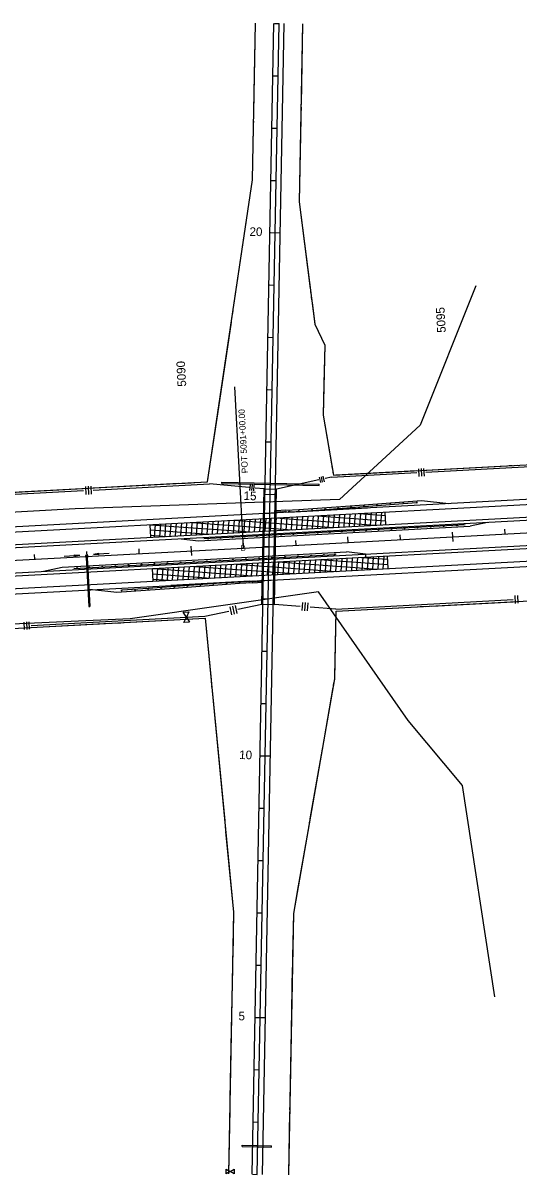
# Model space of a CAD drawing. Extents: x 192699 to 285914, y 194342 to 233219.
# Drawn here: x 253319 to 254267, y 223744 to 225946 of the extents above; entities that cross this region are included whole.
import ezdxf

# ---------------------------------------------------------------- set-up
doc = ezdxf.new("R2010")
doc.units = 0
for name, color, linetype in [('CENT LINE', 7, 'Continuous'), ('CURVE DATA', 7, 'Continuous'), ('DRAINAGE', 7, 'Continuous'), ('DRAINAGE ARROWS', 7, 'Continuous'), ('Flood Plain', 7, 'Continuous'), ('GUARDRAIL', 7, 'Continuous'), ('PAVEMENT TRANSITION', 7, 'Continuous'), ('R-W - CofA', 7, 'Continuous'), ('R_Proposed Guardrail', 7, 'Continuous'), ('R_Water Annot', 7, 'Continuous'), ('ROAD', 7, 'Continuous'), ('SHOULDER', 7, 'Continuous'), ('STATIONING1', 7, 'Continuous'), ('STATIONING2', 7, 'Continuous'), ('TEXT', 7, 'Continuous')]:
    doc.layers.add(name, color=color, linetype=linetype)

msp = doc.modelspace()

# ---------------------------------------------------------------- linework, layer by layer
at = {"layer": 'CENT LINE'}
for p, q in [((253766.8, 223745.2), (253808.4, 225944.8)), ((253740.3, 224942.3), (269263.7, 225774)), ((250998.2, 224795.4), (253740.3, 224942.3))]:
    msp.add_line(p, q, dxfattribs=at)
at = {"layer": 'DRAINAGE'}
for p, q in [((253698.8, 225067.9), (253884.8, 225064.4)), ((253698.8, 225065.4), (253884.7, 225061.9)), ((253439.8, 224924.2), (253444.8, 224830.4)), ((253441.8, 224924.3), (253446.8, 224830.5)), ((253737.8, 223798.5), (253793.8, 223797.4)), ((253737.9, 223801), (253793.9, 223799.9))]:
    msp.add_line(p, q, dxfattribs=at)
for points in [[(253698.8, 225065.4), (253698.8, 225067.9)], [(253884.7, 225061.9), (253884.8, 225064.4)], [(253444.8, 224830.4), (253446.8, 224830.5)], [(253737.8, 223798.5), (253737.9, 223801)], [(253793.8, 223797.4), (253793.9, 223799.9)]]:
    msp.add_lwpolyline(points, dxfattribs=at)
msp.add_lwpolyline([(253438.8, 224924.2), (253442.8, 224924.4), (253442.6, 224928.4), (253438.6, 224928.2)], close=True, dxfattribs=at)
at = {"layer": 'DRAINAGE ARROWS'}
for p, q in [((253417.4, 224929.5), (253427.5, 224928.5)), ((253417.5, 224926.5), (253417.4, 224929.5)), ((253417.4, 224929.3), (253425.8, 224928.5)), ((253417.4, 224929), (253424.1, 224928.4)), ((253417.4, 224928.8), (253422.4, 224928.3)), ((253417.4, 224928.5), (253420.7, 224928.2)), ((253417.5, 224926.5), (253427.5, 224928.5)), ((253417.5, 224926.8), (253425.8, 224928.5)), ((253417.5, 224927), (253424.1, 224928.4)), ((253417.5, 224927.3), (253422.4, 224928.3)), ((253417.5, 224928.3), (253419, 224928.1)), ((253417.5, 224927.5), (253420.7, 224928.2)), ((253417.5, 224927.8), (253419, 224928.1)), ((253463.6, 224932), (253453.7, 224930)), ((253463.8, 224929), (253453.7, 224930)), ((253463.7, 224931.8), (253455.4, 224930.1)), ((253463.8, 224929.3), (253455.4, 224930.1)), ((253463.7, 224931.5), (253457.1, 224930.1)), ((253463.8, 224929.5), (253457.1, 224930.1)), ((253463.7, 224931.3), (253458.8, 224930.2)), ((253463.8, 224929.8), (253458.8, 224930.2)), ((253463.7, 224931), (253460.5, 224930.3)), ((253463.7, 224930), (253460.5, 224930.3)), ((253463.7, 224930.8), (253462.1, 224930.4)), ((253463.7, 224930.3), (253462.1, 224930.4)), ((253463.8, 224929), (253463.6, 224932))]:
    msp.add_line(p, q, dxfattribs=at)
at = {"layer": 'Flood Plain'}
for points in [[(254184.2, 225443.4), (254077.7, 225177), (253923.8, 225034.9), (253418.6, 225017.1), (252417.7, 224961.1), (251507.7, 224918.6), (250580.7, 224854.4), (250428.4, 224837.7), (250447.9, 224645.3)], [(254220.9, 224084.6), (254158.8, 224488.6), (254055.2, 224612.9), (253883.9, 224858.7), (253524.1, 224806.8), (252494.8, 224760.4), (251539.4, 224719), (250710.5, 224664.9), (250448.5, 224645.5)]]:
    msp.add_lwpolyline(points, dxfattribs=at)
at = {"layer": 'GUARDRAIL'}
for p, q in [((253778.7, 225008.5), (253802.7, 225009.8)), ((253826.5, 225011), (253977.4, 225019.1)), ((253752.5, 224878.9), (253601.5, 224870.8)), ((253776.3, 224880.2), (253800.3, 224881.4))]:
    msp.add_line(p, q, dxfattribs=at)
at = {"layer": 'PAVEMENT TRANSITION'}
for p, q in [((253862.1, 224978.9), (253863.9, 225003)), ((253872.2, 224979.4), (253873.9, 225003.6)), ((253881.4, 225004), (254012.2, 224994.5)), ((253882.3, 224980), (253884, 225004.1)), ((253892.3, 224980.5), (253894.1, 225004.6)), ((253902.4, 224981), (253904.1, 225005.2)), ((253912.5, 224981.6), (253914.2, 225005.7)), ((253922.5, 224982.1), (253924.3, 225006.3)), ((253932.6, 224982.7), (253934.3, 225006.8)), ((253942.7, 224983.2), (253944.4, 225007.3)), ((253952.7, 224983.7), (253954.5, 225007.9)), ((253961.2, 225008.2), (254011.6, 225004.6)), ((253962.8, 224984.3), (253964.5, 225008.4)), ((253972.9, 224984.8), (253974.6, 225009)), ((253982.9, 224985.4), (253984.7, 225009.5)), ((253993, 224985.9), (253994.7, 225010)), ((254003, 224986.4), (254004.8, 225010.6)), ((254012.6, 224987), (254011.3, 225010.9)), ((253563.2, 224962.9), (253561.9, 224986.8)), ((253561.9, 224986.8), (253561.9, 224986.8)), ((253561.9, 224986.8), (253561.9, 224986.8)), ((253561.9, 224986.8), (253753.4, 224973.1)), ((253570.3, 224963.3), (253572, 224987.4)), ((253580.3, 224963.8), (253582.1, 224987.9)), ((253590.4, 224964.3), (253592.1, 224988.5)), ((253600.5, 224964.9), (253602.2, 224989)), ((253610.5, 224965.4), (253612.3, 224989.5)), ((253620.6, 224966), (253622.3, 224990.1)), ((253630.7, 224966.5), (253632.4, 224990.6)), ((253640.7, 224967), (253642.5, 224991.2)), ((253641.8, 224991.1), (253833.2, 224977.3)), ((253650.8, 224967.6), (253652.5, 224991.7)), ((253660.8, 224968.1), (253662.6, 224992.2)), ((253670.9, 224968.6), (253672.7, 224992.8)), ((253681, 224969.2), (253682.7, 224993.3)), ((253691, 224969.7), (253692.8, 224993.9)), ((253701.1, 224970.3), (253702.8, 224994.4)), ((253711.2, 224970.8), (253712.9, 224994.9)), ((253721.2, 224971.3), (253723, 224995.5)), ((253721.7, 224995.4), (253913.1, 224981.6)), ((253731.3, 224971.9), (253733, 224996)), ((253741.4, 224972.4), (253743.1, 224996.5)), ((253751.4, 224973), (253753.2, 224997.1)), ((253761.5, 224973.5), (253763.2, 224997.6)), ((253771.6, 224974), (253773.3, 224998.2)), ((253781.6, 224974.6), (253783.4, 224998.7)), ((253791.7, 224975.1), (253793.4, 224999.2)), ((253801.5, 224999.7), (253992.9, 224985.9)), ((253801.8, 224975.7), (253803.5, 224999.8)), ((253811.8, 224976.2), (253813.6, 225000.3)), ((253821.9, 224976.7), (253823.6, 225000.9)), ((253831.9, 224977.3), (253833.7, 225001.4)), ((253842, 224977.8), (253843.7, 225001.9)), ((253852.1, 224978.4), (253853.8, 225002.5)), ((253562.5, 224976.8), (253673.5, 224968.8)), ((253563, 224966.7), (253593.7, 224964.5)), ((253786.1, 224890.7), (253787.9, 224914.8)), ((253796.2, 224891.2), (253797.9, 224915.4)), ((253806, 224915.8), (253997.4, 224902)), ((253806.2, 224891.8), (253808, 224915.9)), ((253816.3, 224892.3), (253818, 224916.4)), ((253826.4, 224892.9), (253828.1, 224917)), ((253836.4, 224893.4), (253838.2, 224917.5)), ((253846.5, 224893.9), (253848.2, 224918.1)), ((253856.6, 224894.5), (253858.3, 224918.6)), ((253866.6, 224895), (253868.4, 224919.1)), ((253876.7, 224895.6), (253878.4, 224919.7)), ((253885.9, 224920.1), (254016.7, 224910.7)), ((253886.8, 224896.1), (253888.5, 224920.2)), ((253896.8, 224896.6), (253898.6, 224920.8)), ((253906.9, 224897.2), (253908.6, 224921.3)), ((253917, 224897.7), (253918.7, 224921.8)), ((253927, 224898.2), (253928.8, 224922.4)), ((253937.1, 224898.8), (253938.8, 224922.9)), ((253947.2, 224899.3), (253948.9, 224923.5)), ((253957.2, 224899.9), (253959, 224924)), ((253965.7, 224924.4), (254016.1, 224920.7)), ((253967.3, 224900.4), (253969, 224924.5)), ((253977.3, 224900.9), (253979.1, 224925.1)), ((253987.4, 224901.5), (253989.1, 224925.6)), ((253997.5, 224902), (253999.2, 224926.2)), ((254007.5, 224902.6), (254009.3, 224926.7)), ((254017.1, 224903.1), (254015.8, 224927)), ((253567.7, 224879), (253566.4, 224903)), ((253566.4, 224903), (253566.4, 224903)), ((253566.4, 224903), (253566.4, 224903)), ((253566.4, 224903), (253757.9, 224889.2)), ((253567, 224892.9), (253678, 224884.9)), ((253574.8, 224879.4), (253576.5, 224903.5)), ((253584.8, 224879.9), (253586.6, 224904)), ((253594.9, 224880.5), (253596.6, 224904.6)), ((253605, 224881), (253606.7, 224905.1)), ((253615, 224881.5), (253616.8, 224905.7)), ((253625.1, 224882.1), (253626.8, 224906.2)), ((253635.1, 224882.6), (253636.9, 224906.7)), ((253645.2, 224883.1), (253646.9, 224907.3)), ((253646.3, 224907.2), (253837.7, 224893.5)), ((253655.3, 224883.7), (253657, 224907.8)), ((253665.3, 224884.2), (253667.1, 224908.4)), ((253675.4, 224884.8), (253677.1, 224908.9)), ((253685.5, 224885.3), (253687.2, 224909.4)), ((253695.5, 224885.8), (253697.3, 224910)), ((253705.6, 224886.4), (253707.3, 224910.5)), ((253715.7, 224886.9), (253717.4, 224911.1)), ((253725.7, 224887.5), (253727.5, 224911.6)), ((253726.1, 224911.5), (253917.6, 224897.7)), ((253735.8, 224888), (253737.5, 224912.1)), ((253745.9, 224888.5), (253747.6, 224912.7)), ((253755.9, 224889.1), (253757.7, 224913.2)), ((253766, 224889.6), (253767.7, 224913.7)), ((253776.1, 224890.2), (253777.8, 224914.3)), ((253567.5, 224882.8), (253598.2, 224880.6))]:
    msp.add_line(p, q, dxfattribs=at)
at = {"layer": 'R-W - CofA'}
for p, q in [((253757.7, 225645.7), (253763.4, 225945.6)), ((253853.4, 225943.9), (253847, 225604)), ((254074.9, 225093.9), (254075.7, 225079.2)), ((254079.8, 225094.1), (254080.6, 225079.5)), ((254084.7, 225094.4), (254085.5, 225079.7)), ((253887.9, 225067.2), (253885.6, 225077.9)), ((253891.4, 225068), (253889.2, 225078.6)), ((253895, 225068.7), (253892.8, 225079.4)), ((253438.2, 225060), (253439, 225044.4)), ((253443.4, 225060.2), (253444.2, 225044.7)), ((253448.6, 225060.5), (253449.4, 225044.9)), ((253752.8, 225052.3), (253753.8, 225063.1)), ((253756.5, 225051.9), (253757.4, 225062.8)), ((253760.1, 225051.6), (253761, 225062.5)), ((254259, 224851.3), (254259.8, 224836.5)), ((254264, 224851.6), (254264.8, 224836.8)), ((253714.3, 224830.1), (253717.6, 224814.8)), ((253719.4, 224831.2), (253722.7, 224815.9)), ((253724.5, 224832.2), (253727.8, 224817)), ((253848.7, 224830.8), (253799.4, 224834.6)), ((253852.4, 224822.7), (253853.6, 224838.3)), ((253857.6, 224822.3), (253858.8, 224837.9)), ((253862.8, 224821.9), (253864, 224837.5)), ((253917, 224825.6), (253867.7, 224829.4)), ((253625, 224819.4), (253636.2, 224820)), ((253631.2, 224810), (253625, 224819.4)), ((253626.1, 224800), (253631.2, 224810)), ((253636.2, 224820), (253631.2, 224810)), ((253631.2, 224810), (253637.3, 224800.6)), ((253320.7, 224800.6), (253321.4, 224786.4)), ((253325.4, 224800.9), (253326.2, 224786.6)), ((253330.2, 224801.1), (253331, 224786.9)), ((253637.3, 224800.6), (253626.1, 224800)), ((253721.3, 224246.1), (253711.8, 223746.2)), ((253826.8, 223744), (253836.3, 224243.9)), ((253707.2, 223746.3), (253707.3, 223755.1)), ((253714.9, 223750.6), (253707.2, 223746.3)), ((253707.3, 223755.1), (253714.9, 223750.6)), ((253714.9, 223750.6), (253722.6, 223754.8)), ((253722.5, 223746), (253714.9, 223750.6)), ((253722.6, 223754.8), (253722.5, 223746))]:
    msp.add_line(p, q, dxfattribs=at)
for points in [[(253760.2, 225775.2), (253763.4, 225945.6)], [(253853.4, 225943.9), (253850.5, 225789.7)], [(253850.2, 225773.8), (253850.1, 225767.8)], [(253850.4, 225784.7), (253850.3, 225778.7)], [(253759.8, 225752), (253759.9, 225758.3)], [(253760, 225763.6), (253760.1, 225769.9)], [(253850, 225762.9), (253847, 225604)], [(253757.7, 225645.7), (253759.7, 225746.7)], [(253671.8, 225068.8), (253757.7, 225645.7)], [(253721.5, 225402.1), (253757.7, 225645.7)], [(253847, 225604), (253876.5, 225370.3), (253895.6, 225330.2), (253892.7, 225195.9), (253912.1, 225081.7)], [(253847, 225604), (253867.9, 225438.1)], [(253868.5, 225433.1), (253869.3, 225427.2)], [(253869.9, 225422.3), (253870.6, 225416.4)], [(253871.3, 225411.5), (253876.5, 225370.3), (253895.6, 225330.2), (253894, 225256.1)], [(253718, 225379.1), (253719, 225385.3)], [(253719.7, 225390.6), (253720.7, 225396.8)], [(253693, 225211.3), (253717.3, 225373.8)], [(253894, 225256.1), (253892.7, 225195.9), (253908.5, 225103.2)], [(253645.5, 225067.4), (253671.8, 225068.8), (253693, 225211.3)], [(253912.1, 225081.7), (255693.6, 225177.2)], [(253909.3, 225098.3), (253910.3, 225092.4)], [(254088.8, 225091.2), (254242.8, 225099.4)], [(254089, 225087.3), (254429.6, 225105.5)], [(254247.8, 225099.7), (254253.7, 225100)], [(254258.7, 225100.3), (254264.6, 225100.6)], [(250990.2, 224945.2), (251136, 224953), (251636.3, 224959.8), (252535, 225007.9), (252634.4, 225023.3), (252933.9, 225039.3), (253034.3, 225034.7), (253671.8, 225068.8)], [(253884.6, 225072.4), (253803.6, 225054.9)], [(253908.8, 225077.6), (253896.3, 225074.9)], [(253908.8, 225077.6), (254071.4, 225086.3)], [(253911.1, 225087.5), (253912.1, 225081.7), (253912.2, 225081.7)], [(253917.1, 225082), (254071.2, 225090.2)], [(253077.8, 225032.8), (253434.4, 225052)], [(253270.1, 225047.3), (253434.2, 225056.1)], [(253452.9, 225057.1), (253617, 225065.9)], [(253453.1, 225053), (253675.4, 225064.9)], [(253622.3, 225066.2), (253628.6, 225066.5)], [(253633.9, 225066.8), (253640.2, 225067.1)], [(253750.9, 225057.9), (253675.4, 225064.9)], [(253779.6, 225055.3), (253762.9, 225056.8)], [(253917.2, 224821.6), (255810.1, 224923)], [(253729.6, 224825.4), (253775.4, 224835.1)], [(253917, 224825.6), (254255.5, 224843.7)], [(253917.2, 224821.6), (254072.9, 224830)], [(254077.9, 224830.2), (254083.9, 224830.5)], [(254089, 224830.8), (254095, 224831.1)], [(254100, 224831.4), (254255.7, 224839.7)], [(251152, 224653.4), (251650.2, 224700.2), (252548.9, 224748.3), (252649.3, 224743.7), (252948.9, 224759.7), (253048.2, 224775.1), (253666.9, 224808.2)], [(253334.4, 224794.2), (253666.7, 224812)], [(253511, 224799.9), (253666.9, 224808.2)], [(253666.7, 224812), (253712.1, 224821.6)], [(253666.9, 224808.2), (253721.3, 224246.1)], [(253666.9, 224808.2), (253678.3, 224690.4)], [(253836.3, 224243.9), (253914.8, 224692.5), (253917.2, 224821.6)], [(253914.8, 224696.6), (253917.2, 224821.6)], [(253334.6, 224790.4), (253484.9, 224798.5)], [(253489.7, 224798.7), (253495.5, 224799)], [(253500.4, 224799.3), (253506.1, 224799.6)], [(253678.7, 224686.6), (253679.1, 224682.1)], [(253679.5, 224678.3), (253679.9, 224673.7)], [(253891.1, 224557.2), (253911.8, 224675.9)], [(253912.5, 224679.7), (253913.3, 224684.3)], [(253914, 224688.1), (253914.8, 224692.5), (253914.8, 224692.7)], [(253680.3, 224670), (253691.7, 224552.2)], [(253691.7, 224552.2), (253704.4, 224421)], [(253867.9, 224424.9), (253891.1, 224557.6)], [(253704.7, 224417.2), (253705.2, 224412.6)], [(253705.5, 224408.8), (253706, 224404.3)], [(253865, 224408.1), (253865.8, 224412.7)], [(253866.5, 224416.5), (253867.3, 224421.1)], [(253706.3, 224400.5), (253718.2, 224278.3)], [(253843.5, 224285.6), (253864.3, 224404.3)], [(253718.2, 224278.3), (253721.3, 224246.1), (253719.7, 224160.2)], [(253834.7, 224161.2), (253836.3, 224243.9), (253843.5, 224285.6)], [(253719.4, 224148), (253719.3, 224143.4)], [(253719.6, 224156.3), (253719.5, 224151.8)], [(253834.4, 224144.1), (253834.5, 224148.8)], [(253834.5, 224152.7), (253834.6, 224157.3)], [(253719.3, 224139.6), (253717, 224021.3)], [(253832, 224019.7), (253834.3, 224140.3)], [(253717, 224021.2), (253714.5, 223889.5)], [(253829.5, 223885.5), (253832, 224019.9)], [(253714.5, 223885.7), (253714.4, 223881.1)], [(253829.3, 223877), (253829.4, 223881.6)], [(253714.1, 223868.9), (253711.8, 223746.2)], [(253714.3, 223877.3), (253714.2, 223872.7)], [(253826.8, 223744), (253829.1, 223864.6)], [(253829.2, 223868.4), (253829.2, 223873.1)]]:
    msp.add_lwpolyline(points, dxfattribs=at)
at = {"layer": 'R_Proposed Guardrail'}
for p, q in [((253846.2, 225015.7), (253970.8, 225025.1)), ((253846.4, 225012.2), (254020.9, 225025.4)), ((253970.8, 225025.1), (254080.5, 225033.4)), ((254020.9, 225025.4), (254070.8, 225029.1)), ((254072.5, 225030.3), (254070.8, 225029.1)), ((254072.6, 225028.3), (254070.8, 225029.1)), ((254072.6, 225028.3), (254072.5, 225030.3)), ((254080.5, 225033.4), (254133.1, 225027.6)), ((253821.3, 225014.3), (253802.5, 225013.3)), ((253821.5, 225010.8), (253802.7, 225009.8)), ((253821.3, 225014.3), (253846.2, 225015.7)), ((253821.5, 225010.8), (253846.4, 225012.2)), ((253654.4, 224956.2), (254173.7, 224984)), ((253664.5, 224960.5), (254163.7, 224987.2)), ((254206.4, 224991.3), (254173.7, 224984)), ((253621.2, 224959.9), (253654.4, 224956.2)), ((253393.6, 224905.7), (253937.2, 224934.8)), ((253416.2, 224902.9), (253915.5, 224929.7)), ((253973.5, 224930.8), (253937.2, 224934.8)), ((253973.5, 224930.8), (253973.8, 224924.8)), ((253358, 224897.8), (253393.6, 224905.7)), ((253732.6, 224877.8), (253558, 224865.1)), ((253732.8, 224874.4), (253608.2, 224865.2)), ((253757.6, 224879.2), (253732.6, 224877.8)), ((253757.7, 224875.7), (253732.8, 224874.3)), ((253757.6, 224879.2), (253776.3, 224880.2)), ((253757.7, 224875.7), (253776.5, 224876.7)), ((253498.4, 224857.2), (253445.9, 224863.1)), ((253608.2, 224865.2), (253498.4, 224857.2)), ((253506.4, 224862.3), (253508.2, 224861.4)), ((253506.4, 224862.3), (253506.5, 224860.3)), ((253506.5, 224860.3), (253508.2, 224861.4)), ((253558, 224865.1), (253508.2, 224861.4))]:
    msp.add_line(p, q, dxfattribs=at)
for centre in [(253996, 225024.2), (254020.9, 225026.1), (254045.8, 225028), (253804.3, 225010.6), (253805.8, 225010.7), (253807.4, 225010.8), (253808.9, 225010.9), (253810.5, 225010.9), (253812.1, 225011), (253815.2, 225011.2), (253818.3, 225011.4), (253821.4, 225011.5), (253827.7, 225011.9), (253846.4, 225012.9), (253871.3, 225014.8), (253896.3, 225016.7), (253921.2, 225018.6), (253946.1, 225020.5), (253971, 225022.3), (254048.1, 224980), (254073.1, 224981.4), (254098.1, 224982.7), (254123, 224984.1), (254148, 224985.4), (253673, 224960.2), (253696.2, 224961.4), (253719.5, 224962.7), (253742.7, 224963.9), (253765.9, 224965.1), (253789.2, 224966.3), (253812.4, 224967.6), (253835.6, 224968.8), (253858.8, 224970), (253882.1, 224971.2), (253905.3, 224972.5), (253928.5, 224973.7), (253951.8, 224974.9), (253975, 224976.1), (253998.2, 224977.4), (254023.2, 224978.7), (253620.3, 224914.6), (253645.3, 224916), (253670.2, 224917.3), (253695.2, 224918.6), (253720.2, 224920), (253745.1, 224921.3), (253770.1, 224922.6), (253795.1, 224924), (253820, 224925.3), (253845, 224926.7), (253869.9, 224928), (253893.9, 224929.3), (253915.4, 224930.4), (253422.3, 224904), (253445.6, 224905.3), (253470.5, 224906.6), (253495.5, 224907.9), (253520.4, 224909.3), (253545.4, 224910.6), (253570.4, 224911.9), (253595.3, 224913.3), (253657.8, 224871.6), (253682.7, 224873.4), (253707.7, 224875.3), (253732.6, 224877.1), (253751.4, 224878.1), (253757.6, 224878.4), (253760.7, 224878.6), (253763.8, 224878.7), (253767, 224878.9), (253768.5, 224879), (253770.1, 224879.1), (253771.6, 224879.2), (253773.2, 224879.2), (253774.8, 224879.3), (253533.1, 224862.5), (253558, 224864.3), (253583, 224866.2), (253607.9, 224868), (253632.9, 224869.8)]:
    msp.add_circle(centre, 0.75, dxfattribs=at)
at = {"layer": 'R_Water Annot'}
for p, q in [((253397.5, 224927), (253427.5, 224928.5)), ((253417.4, 224929.5), (253427.5, 224928.5)), ((253417.5, 224926.5), (253417.4, 224929.5)), ((253417.4, 224929.3), (253425.8, 224928.5)), ((253417.4, 224929), (253424.1, 224928.4)), ((253417.4, 224928.8), (253422.4, 224928.3)), ((253417.4, 224928.5), (253420.7, 224928.2)), ((253417.5, 224926.5), (253427.5, 224928.5)), ((253417.5, 224926.8), (253425.8, 224928.5)), ((253417.5, 224927), (253424.1, 224928.4)), ((253417.5, 224927.3), (253422.4, 224928.3)), ((253417.5, 224928.3), (253419, 224928.1)), ((253417.5, 224927.5), (253420.7, 224928.2)), ((253417.5, 224927.8), (253419, 224928.1)), ((253463.6, 224932), (253453.7, 224930)), ((253483.7, 224931.6), (253453.7, 224930)), ((253463.8, 224929), (253453.7, 224930)), ((253463.7, 224931.8), (253455.4, 224930.1)), ((253463.8, 224929.3), (253455.4, 224930.1)), ((253463.7, 224931.5), (253457.1, 224930.1)), ((253463.8, 224929.5), (253457.1, 224930.1)), ((253463.7, 224931.3), (253458.8, 224930.2)), ((253463.8, 224929.8), (253458.8, 224930.2)), ((253463.7, 224931), (253460.5, 224930.3)), ((253463.7, 224930), (253460.5, 224930.3)), ((253463.7, 224930.8), (253462.1, 224930.4)), ((253463.7, 224930.3), (253462.1, 224930.4)), ((253463.8, 224929), (253463.6, 224932))]:
    msp.add_line(p, q, dxfattribs=at)
at = {"layer": 'ROAD'}
for p, q in [((253756.8, 223745.4), (253798.4, 225945)), ((253776.8, 223745), (253818.4, 225944.6)), ((250995.3, 224849.3), (255646.7, 225098.5)), ((253775.4, 224835.1), (253779.6, 225055.3)), ((253799.4, 224834.6), (253803.6, 225054.9)), ((250996.6, 224825.4), (255085.2, 225044.4)), ((251001.1, 224741.5), (256101.5, 225014.7)), ((250999.8, 224765.5), (255121.9, 224986.3))]:
    msp.add_line(p, q, dxfattribs=at)
for points in [[(253779.6, 225055.3), (253803.6, 225054.9)], [(253775.4, 224835.1), (253799.4, 224834.6)]]:
    msp.add_lwpolyline(points, dxfattribs=at)
at = {"layer": 'SHOULDER'}
for p, q in [((250994.8, 224859.3), (255026.1, 225075.3)), ((250996.9, 224819.4), (255003.7, 225034)), ((250999.5, 224771.4), (255006.2, 224986.1)), ((251001.6, 224731.5), (255104.4, 224951.3))]:
    msp.add_line(p, q, dxfattribs=at)
at = {"layer": 'STATIONING1'}
for points in [[(253939.4, 224963.5), (253940, 224953)], [(254039.4, 224967.4), (254039.8, 224958.4)], [(254139.2, 224972.7), (254140.2, 224954.7)], [(254239.1, 224978.1), (254239.6, 224969.1)], [(253540.1, 224940.6), (253540.6, 224931.6)], [(253639.9, 224946), (253640.9, 224928)], [(253739.8, 224951.3), (253740.3, 224942.3)], [(253839.7, 224956.7), (253840.1, 224947.7)], [(253340.4, 224929.9), (253340.9, 224920.9)], [(253440.2, 224935.3), (253440.7, 224926.3)]]:
    msp.add_lwpolyline(points, dxfattribs=at)
at = {"layer": 'STATIONING2'}
for points in [[(253799.4, 225944.9), (253808.4, 225944.8)], [(253799.4, 225944.9), (253808.4, 225944.8)], [(253797.5, 225845), (253806.5, 225844.8)], [(253795.6, 225745), (253804.6, 225744.8)], [(253793.7, 225645), (253802.7, 225644.8)], [(253791.9, 225545), (253809.8, 225544.7)], [(253790, 225445), (253799, 225444.9)], [(253788.1, 225345.1), (253797.1, 225344.9)], [(253786.2, 225245.1), (253795.2, 225244.9)], [(253784.3, 225145.1), (253793.3, 225144.9)], [(253782.4, 225045.1), (253800.4, 225044.8)], [(253780.5, 224945.1), (253789.5, 224945)], [(253778.6, 224845.1), (253787.6, 224845)], [(253776.7, 224745.2), (253785.7, 224745)], [(253774.8, 224645.2), (253783.8, 224645)], [(253772.9, 224545.2), (253790.9, 224544.9)], [(253771.1, 224445.2), (253780.1, 224445)], [(253769.2, 224345.2), (253778.2, 224345.1)], [(253767.3, 224245.3), (253776.3, 224245.1)], [(253765.4, 224145.3), (253774.4, 224145.1)], [(253763.5, 224045.3), (253781.5, 224044.9)], [(253761.6, 223945.3), (253770.6, 223945.1)], [(253759.7, 223845.3), (253768.7, 223845.2)], [(253757.8, 223745.3), (253766.8, 223745.2)]]:
    msp.add_lwpolyline(points, dxfattribs=at)
at = {"layer": 'TEXT'}
msp.add_lwpolyline([(253740.3, 224942.3), (253723.8, 225250.5)], dxfattribs=at)

# ---------------------------------------------------------------- texts
at = {"layer": 'CURVE DATA'}
msp.add_text('B', height=10.8, rotation=3.0667, dxfattribs=at).set_placement((253735.1, 224936.6))
at = {"layer": 'STATIONING1'}
for s, p in [('5095', (254127.1, 225354)), ('5090', (253631, 225251.1))]:
    msp.add_text(s, height=16.5, rotation=93.0667, dxfattribs=at).set_placement(p)
at = {"layer": 'STATIONING2'}
for s, p in [('20', (253751.8, 225538.8)), ('15', (253740.5, 225034)), ('10', (253732.1, 224538.9)), ('5', (253730.7, 224039.7))]:
    msp.add_text(s, height=16.5, rotation=358.9167, dxfattribs=at).set_placement(p)
at = {"layer": 'TEXT'}
msp.add_text('POT 5091+00.00', height=12, rotation=93.0667, dxfattribs=at).set_placement((253749.1, 225085.5))

doc.saveas('drawing.dxf')
